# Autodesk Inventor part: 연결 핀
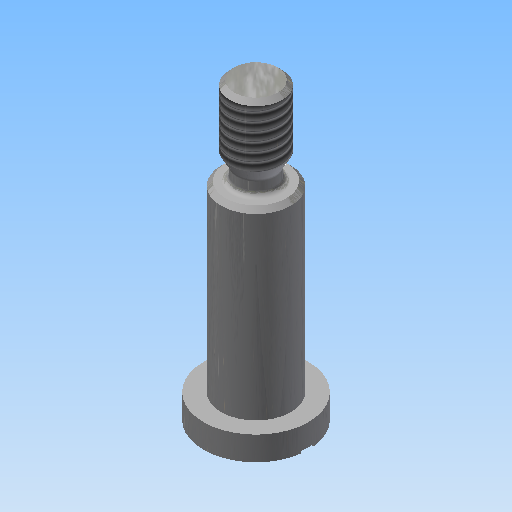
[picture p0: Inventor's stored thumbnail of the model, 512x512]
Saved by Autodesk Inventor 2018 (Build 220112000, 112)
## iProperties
Created: 2022-09
Part Number: 연결 핀
Material: 강철, 연강
Document SubType Name: Modeling
Designer: mdu-01
Density: 7.86 g/cm^3
Mass: 13.1021 g
Surface Area: 10.634 cm^2
Volume: 1.66693 cm^3
Appearance: 강철
Author: mdu-01
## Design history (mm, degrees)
sketch "스케치1"
  geometry: L1 (0, 0)-(35, 0); L2 (35, 0)-(35, 3); L3 (35, 3)-(27.986, 3); L4 (25, 2.2)-(25, 4); L5 (25, 4)-(4, 4); L6 (4, 4)-(4, 6); L7 (4, 6)-(1.252, 6); L8 (0, 6)-(0, 0); L9 (27.986, 3)-(26.6, 2.2); L10 (26.6, 2.2)-(25, 2.2); A1 r 15 centre (15, 0) between (1.252, 6) and (0, 0)
  constraints: 20 end point, 4 horizontal, 4 perpendicular, 2 point on circle, 1 centre point, 1 parallel, 1 point on line
  dimensions: "d1" = 6 diameter of L3 L1; "d3" = 8 diameter of L5 L1; "d4" = 10 distance between parallel lines of L4 L2; "d5" = 21 distance between parallel lines of L6 L4; "d6" = 4 distance between parallel lines of L8 L6; "d7" = 12 diameter of L7 L1; "d8" = 4.4 diameter of L10 L1; "d9" = 1.6 distance of L9.end L4.start; "d10" = 30 deg angle of L3 L9; "d14" = 15 radius of A1
revolve "회전1" sketch "스케치1" stored, may be unused: angle "d11" = 90 deg
fillet "모깎기1" dims "d12" = 0.6
sketch "스케치2"
  geometry: L1 (0, 0.75)-(1.5, 0.75); L2 (1.5, 0.75)-(1.5, -0.75); L3 (1.5, -0.75)-(0, -0.75); L4 (0, -0.75)-(0, 0.75); 2 further points
  constraints: 8 end point, 2 parallel, 2 perpendicular, 1 coincident, 1 horizontal, 1 midpoint
  dimensions: "d15" = 1.5 distance between parallel lines of L3 L1
extrude "돌출1" cut sketch "스케치2" extent not by distance; stored distance "d17" = 10; taper "d18" = 0 deg
feature "스레드1" dims "d20" = 10, "d21" = 0
chamfer "모따기1" distance "d22" = 0.5; stored, may be unused: second distance "d23" = 2, angle "d24" = 45 deg
node "솔리드1"
